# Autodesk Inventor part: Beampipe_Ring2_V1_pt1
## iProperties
Shininess: 64.0
Length Units: 11269
Angle Units: 11279
Time Units: 11290
Mass Units: 11283
Length Display Precision: 3
Angle Display Precision: 2
Compacted: True
Part Number: Beampipe_Ring2_V1_pt1
Document SubType Name: Modeling
Created: 2004-08
Designer: John Blackburn
Manufacturer: Standard
Standards Organization: Custom
Material: Aluminum-6061
Density: 0.0
Volumn: 0.0
Area: 0.0
PropertySet Name: Model Information
Control State: 0
Master: False
Checked Out: False
Author: John Blackburn
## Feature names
1. Extrusion1
2. Split1
3. Hole6
4. Hole7
5. Extrusion8
6. Extrusion9
7. Hole11
8. Extrusion10
9. Hole12
10. Hole13
